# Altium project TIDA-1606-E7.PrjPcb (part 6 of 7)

## Sheet TIDA-1606-Control-Interface-E7.SchDoc
size A2; Date: Not shown in title block; ApprovedBy: Not shown in title block; CheckedBy: Not shown in title block; Author: Not shown in title block; CompanyName: Not shown in title block; Engineer: Not shown in title block; Organization: Not shown in title block; Address1: Not shown in title block; Address2: Not shown in title block; Address3: Not shown in title block; Address4: Not shown in title block; DocumentNumber: 16; Revision: Use project parameter SCH_Rev; SheetNumber: 16; SheetTotal: 16; PageSetup: Record=PageOptions¦CenterHorizontal=True¦CenterVertical=True¦PrintScale=0.69¦XCorrection=1.00¦YCorrection=1.00¦PrintKind=0¦BorderSize=5000000¦LeftOffset=0¦BottomOffset=0¦Orientation=2¦PaperLength=1000¦PaperWidth=1000¦Scale=100¦PaperSource=15¦PrintQuality=600¦MediaType=1¦DitherType=10¦PaperKind=Letter¦PrintScaleMode=1
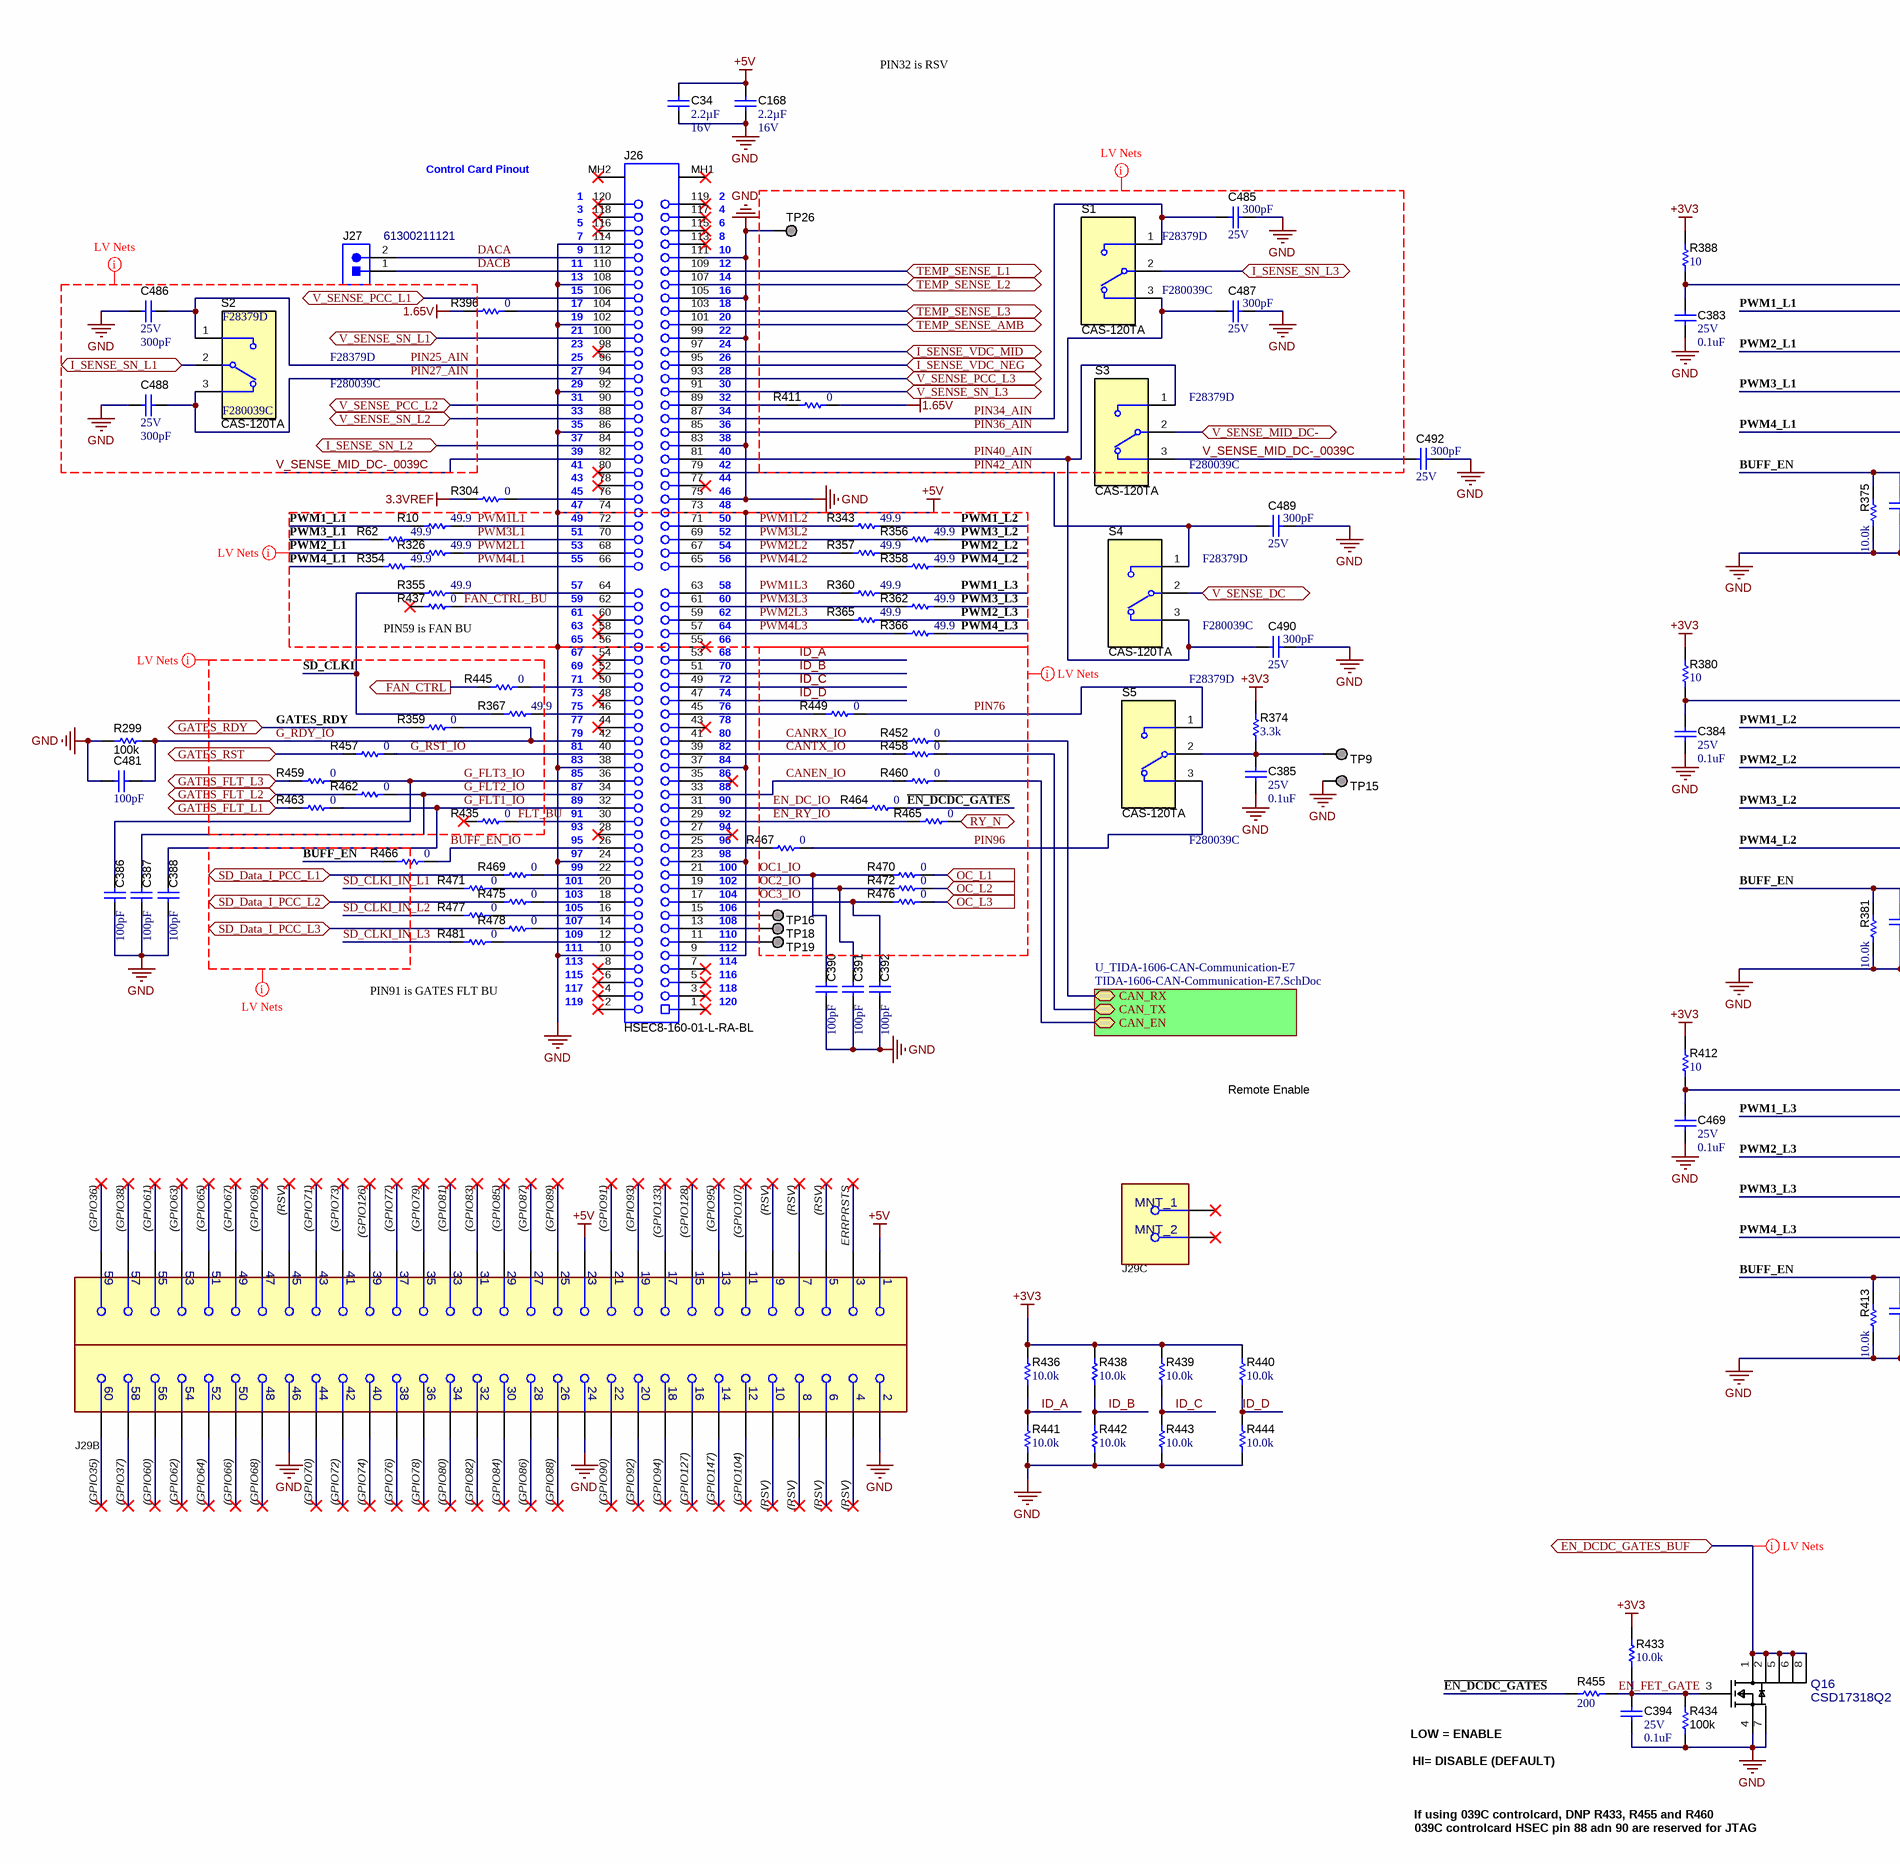
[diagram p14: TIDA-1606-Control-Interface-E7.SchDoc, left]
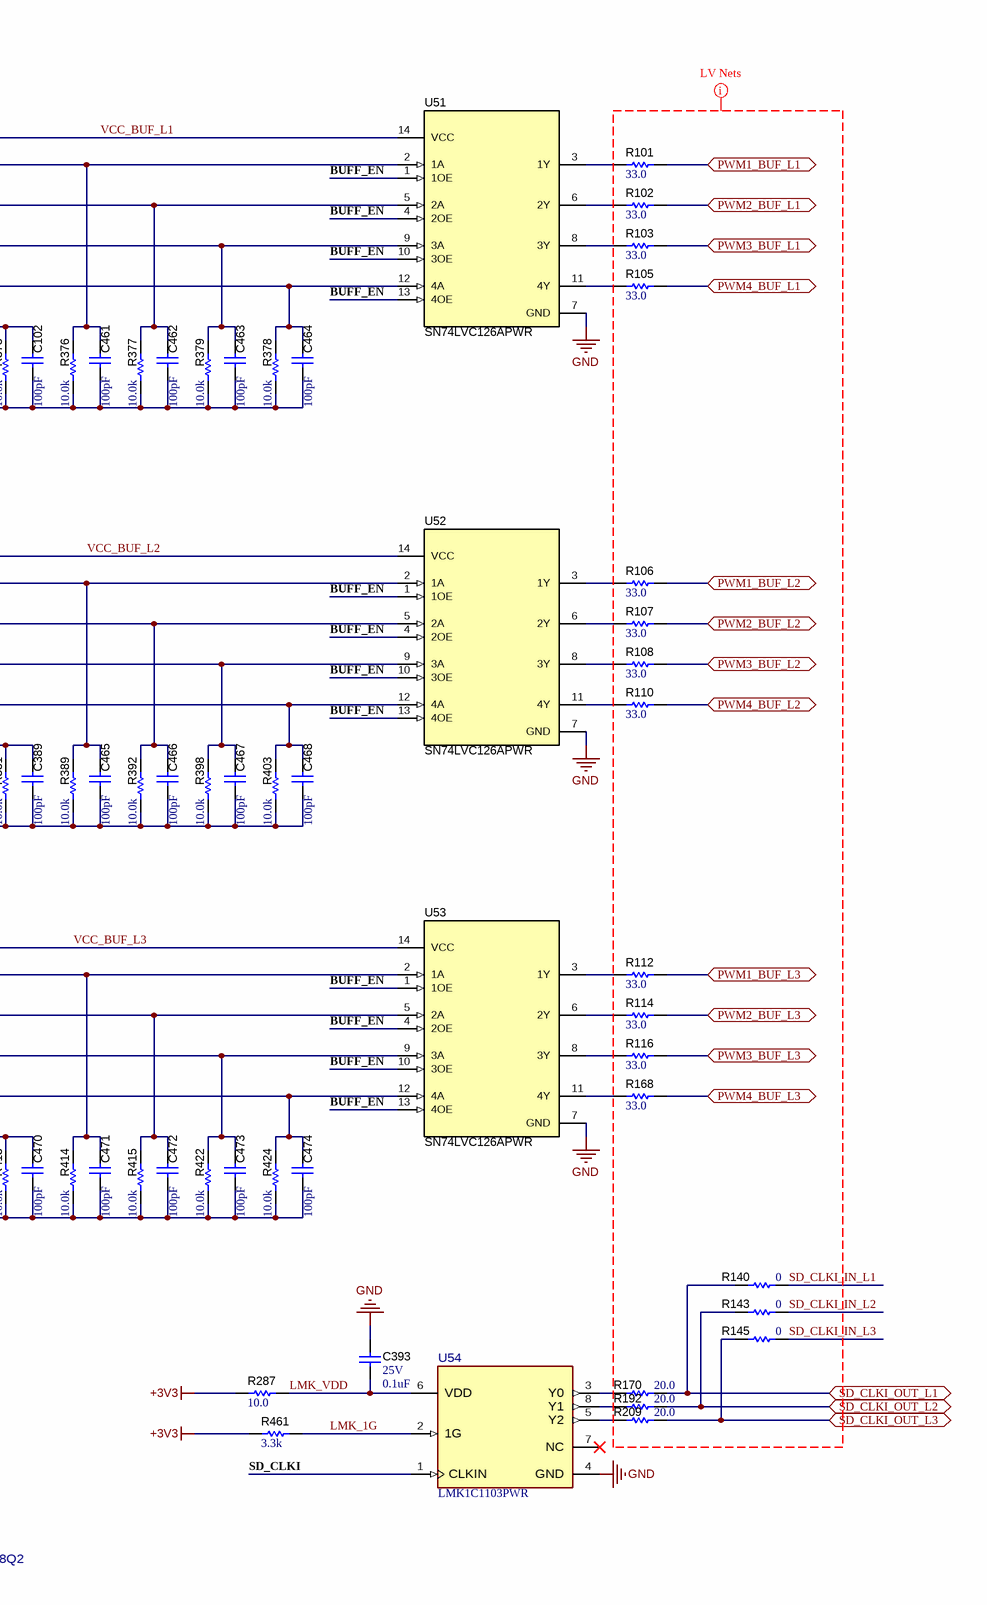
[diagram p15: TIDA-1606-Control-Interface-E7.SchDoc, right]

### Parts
C34  Cap_F: 2.2µF  VDC_V: 16V  [0603L]  (hidden comment: EMK107BB7225KA-T)
C102  ValueDisplayed: 100pF  [0402L]  (hidden comment: GRM1555C1H101JA01D)
C168  Cap_F: 2.2µF  VDC_V: 16V  [0603L]  (hidden comment: EMK107BB7225KA-T)
C383  VDC_V: 25V  ValueDisplayed: 0.1uF  [0402L]  (hidden comment: GRM155R71E104KE14D)
C384  VDC_V: 25V  ValueDisplayed: 0.1uF  [0402L]  (hidden comment: GRM155R71E104KE14D)
C385  VDC_V: 25V  ValueDisplayed: 0.1uF  [0402L]  (hidden comment: GRM155R71E104KE14D)
C386  ValueDisplayed: 100pF  [0402L]  (hidden comment: GRM1555C1H101JA01D)
C387  ValueDisplayed: 100pF  [0402L]  (hidden comment: GRM1555C1H101JA01D)
C388  ValueDisplayed: 100pF  [0402L]  (hidden comment: GRM1555C1H101JA01D)
C389  ValueDisplayed: 100pF  [0402L]  (hidden comment: GRM1555C1H101JA01D)
C390  ValueDisplayed: 100pF  [0402L]  (hidden comment: GRM1555C1H101JA01D)
C391  ValueDisplayed: 100pF  [0402L]  (hidden comment: GRM1555C1H101JA01D)
C392  ValueDisplayed: 100pF  [0402L]  (hidden comment: GRM1555C1H101JA01D)
C393  VDC_V: 25V  ValueDisplayed: 0.1uF  [0402L]  (hidden comment: GRM155R71E104KE14D)
C394  VDC_V: 25V  ValueDisplayed: 0.1uF  [0402L]  (hidden comment: GRM155R71E104KE14D)
C461  ValueDisplayed: 100pF  [0402L]  (hidden comment: GRM1555C1H101JA01D)
C462  ValueDisplayed: 100pF  [0402L]  (hidden comment: GRM1555C1H101JA01D)
C463  ValueDisplayed: 100pF  [0402L]  (hidden comment: GRM1555C1H101JA01D)
C464  ValueDisplayed: 100pF  [0402L]  (hidden comment: GRM1555C1H101JA01D)
C465  ValueDisplayed: 100pF  [0402L]  (hidden comment: GRM1555C1H101JA01D)
C466  ValueDisplayed: 100pF  [0402L]  (hidden comment: GRM1555C1H101JA01D)
C467  ValueDisplayed: 100pF  [0402L]  (hidden comment: GRM1555C1H101JA01D)
C468  ValueDisplayed: 100pF  [0402L]  (hidden comment: GRM1555C1H101JA01D)
C469  VDC_V: 25V  ValueDisplayed: 0.1uF  [0402L]  (hidden comment: GRM155R71E104KE14D)
C470  ValueDisplayed: 100pF  [0402L]  (hidden comment: GRM1555C1H101JA01D)
C471  ValueDisplayed: 100pF  [0402L]  (hidden comment: GRM1555C1H101JA01D)
C472  ValueDisplayed: 100pF  [0402L]  (hidden comment: GRM1555C1H101JA01D)
C473  ValueDisplayed: 100pF  [0402L]  (hidden comment: GRM1555C1H101JA01D)
C474  ValueDisplayed: 100pF  [0402L]  (hidden comment: GRM1555C1H101JA01D)
C481  ValueDisplayed: 100pF  [0402L]  (hidden comment: GRM1555C1H101JA01D)
C485  VDC_V: 25V  ValueDisplayed: 300pF  [0402L]  (hidden comment: GRM1555C1E301JA01D)
C486  VDC_V: 25V  ValueDisplayed: 300pF  [0402L]  (hidden comment: GRM1555C1E301JA01D)
C487  VDC_V: 25V  ValueDisplayed: 300pF  [0402L]  (hidden comment: GRM1555C1E301JA01D)
C488  VDC_V: 25V  ValueDisplayed: 300pF  [0402L]  (hidden comment: GRM1555C1E301JA01D)
C489  VDC_V: 25V  ValueDisplayed: 300pF  [0402L]  (hidden comment: GRM1555C1E301JA01D)
C490  VDC_V: 25V  ValueDisplayed: 300pF  [0402L]  (hidden comment: GRM1555C1E301JA01D)
C492  VDC_V: 25V  ValueDisplayed: 300pF  [0402L]  (hidden comment: GRM1555C1E301JA01D)
J26  HSEC8-160-01-L-RA-BL  [Samtec_HSEC8-160-01-x-RA-BL]
J27  61300211121  [WURTH_61300211121]
J29  HSEC8-130-01-L-RA  [FP-HSEC8-130-01-L-RA_HDR60-MFG]  (value not drawn)  (parts A,B,C of 3)
Q16  CSD17318Q2  [FP-CSD17318Q2_WSON6-MFG]
R10  ValueDisplayed: 49.9  [0402L]  (hidden comment: ERJ-2RKF49R9X)
R62  ValueDisplayed: 49.9  [0402L]  (hidden comment: ERJ-2RKF49R9X)
R101  ValueDisplayed: 33.0  [0402L]  (hidden comment: ERJ-2RKF33R0X)
R102  ValueDisplayed: 33.0  [0402L]  (hidden comment: ERJ-2RKF33R0X)
R103  ValueDisplayed: 33.0  [0402L]  (hidden comment: ERJ-2RKF33R0X)
R105  ValueDisplayed: 33.0  [0402L]  (hidden comment: ERJ-2RKF33R0X)
R106  ValueDisplayed: 33.0  [0402L]  (hidden comment: ERJ-2RKF33R0X)
R107  ValueDisplayed: 33.0  [0402L]  (hidden comment: ERJ-2RKF33R0X)
R108  ValueDisplayed: 33.0  [0402L]  (hidden comment: ERJ-2RKF33R0X)
R110  ValueDisplayed: 33.0  [0402L]  (hidden comment: ERJ-2RKF33R0X)
R112  ValueDisplayed: 33.0  [0402L]  (hidden comment: ERJ-2RKF33R0X)
R114  ValueDisplayed: 33.0  [0402L]  (hidden comment: ERJ-2RKF33R0X)
R116  ValueDisplayed: 33.0  [0402L]  (hidden comment: ERJ-2RKF33R0X)
R140  ValueDisplayed: 0  [0402L]  (hidden comment: RC0402JR-070RL)
R143  ValueDisplayed: 0  [0402L]  (hidden comment: RC0402JR-070RL)
R145  ValueDisplayed: 0  [0402L]  (hidden comment: RC0402JR-070RL)
R168  ValueDisplayed: 33.0  [0402L]  (hidden comment: ERJ-2RKF33R0X)
R170  ValueDisplayed: 20.0  [0402L]  (hidden comment: CRCW040220R0FKED)
R192  ValueDisplayed: 20.0  [0402L]  (hidden comment: CRCW040220R0FKED)
R209  ValueDisplayed: 20.0  [0402L]  (hidden comment: CRCW040220R0FKED)
R287  ValueDisplayed: 10.0  [CPF0402]  (hidden comment: CPF0402B10RE1)
R299  ValueDisplayed: 100k  [0402L]  (hidden comment: ERJ-2GEJ104X)
R304  ValueDisplayed: 0  [0402L]  (hidden comment: RC0402JR-070RL)
R326  ValueDisplayed: 49.9  [0402L]  (hidden comment: ERJ-2RKF49R9X)
R343  ValueDisplayed: 49.9  [0402L]  (hidden comment: ERJ-2RKF49R9X)
R354  ValueDisplayed: 49.9  [0402L]  (hidden comment: ERJ-2RKF49R9X)
R355  ValueDisplayed: 49.9  [0402L]  (hidden comment: ERJ-2RKF49R9X)
R356  ValueDisplayed: 49.9  [0402L]  (hidden comment: ERJ-2RKF49R9X)
R357  ValueDisplayed: 49.9  [0402L]  (hidden comment: ERJ-2RKF49R9X)
R358  ValueDisplayed: 49.9  [0402L]  (hidden comment: ERJ-2RKF49R9X)
R359  ValueDisplayed: 0  [0402L]  (hidden comment: RC0402JR-070RL)
R360  ValueDisplayed: 49.9  [0402L]  (hidden comment: ERJ-2RKF49R9X)
R362  ValueDisplayed: 49.9  [0402L]  (hidden comment: ERJ-2RKF49R9X)
R365  ValueDisplayed: 49.9  [0402L]  (hidden comment: ERJ-2RKF49R9X)
R366  ValueDisplayed: 49.9  [0402L]  (hidden comment: ERJ-2RKF49R9X)
R367  ValueDisplayed: 49.9  [0402L]  (hidden comment: ERJ-2RKF49R9X)
R374  ValueDisplayed: 3.3k  [0402L]  (hidden comment: CRCW04023K30JNED)
R375  ValueDisplayed: 10.0k  [0402L]  (hidden comment: CRCW040210K0FKED)
R376  ValueDisplayed: 10.0k  [0402L]  (hidden comment: CRCW040210K0FKED)
R377  ValueDisplayed: 10.0k  [0402L]  (hidden comment: CRCW040210K0FKED)
R378  ValueDisplayed: 10.0k  [0402L]  (hidden comment: CRCW040210K0FKED)
R379  ValueDisplayed: 10.0k  [0402L]  (hidden comment: CRCW040210K0FKED)
R380  ValueDisplayed: 10  [0402L]  (hidden comment: CRCW040210R0JNED)
R381  ValueDisplayed: 10.0k  [0402L]  (hidden comment: CRCW040210K0FKED)
R388  ValueDisplayed: 10  [0402L]  (hidden comment: CRCW040210R0JNED)
R389  ValueDisplayed: 10.0k  [0402L]  (hidden comment: CRCW040210K0FKED)
R392  ValueDisplayed: 10.0k  [0402L]  (hidden comment: CRCW040210K0FKED)
R396  ValueDisplayed: 0  [0402L]  (hidden comment: RC0402JR-070RL)
R398  ValueDisplayed: 10.0k  [0402L]  (hidden comment: CRCW040210K0FKED)
R403  ValueDisplayed: 10.0k  [0402L]  (hidden comment: CRCW040210K0FKED)
R411  ValueDisplayed: 0  [0402L]  (hidden comment: RC0402JR-070RL)
R412  ValueDisplayed: 10  [0402L]  (hidden comment: CRCW040210R0JNED)
R413  ValueDisplayed: 10.0k  [0402L]  (hidden comment: CRCW040210K0FKED)
R414  ValueDisplayed: 10.0k  [0402L]  (hidden comment: CRCW040210K0FKED)
R415  ValueDisplayed: 10.0k  [0402L]  (hidden comment: CRCW040210K0FKED)
R422  ValueDisplayed: 10.0k  [0402L]  (hidden comment: CRCW040210K0FKED)
R424  ValueDisplayed: 10.0k  [0402L]  (hidden comment: CRCW040210K0FKED)
R433  ValueDisplayed: 10.0k  [0402L]  (hidden comment: CRCW040210K0FKED)
R434  ValueDisplayed: 100k  [0402S]  (hidden comment: ERJ-2GEJ104X)
R435  ValueDisplayed: 0  [0402L]  (hidden comment: RC0402JR-070RL)
R436  ValueDisplayed: 10.0k  [0402L]  (hidden comment: CRCW040210K0FKED)
R437  ValueDisplayed: 0  [0402L]  (hidden comment: RC0402JR-070RL)
R438  ValueDisplayed: 10.0k  [0402L]  (hidden comment: CRCW040210K0FKED)
R439  ValueDisplayed: 10.0k  [0402L]  (hidden comment: CRCW040210K0FKED)
R440  ValueDisplayed: 10.0k  [0402L]  (hidden comment: CRCW040210K0FKED)
R441  ValueDisplayed: 10.0k  [0402L]  (hidden comment: CRCW040210K0FKED)
R442  ValueDisplayed: 10.0k  [0402L]  (hidden comment: CRCW040210K0FKED)
R443  ValueDisplayed: 10.0k  [0402L]  (hidden comment: CRCW040210K0FKED)
R444  ValueDisplayed: 10.0k  [0402L]  (hidden comment: CRCW040210K0FKED)
R445  ValueDisplayed: 0  [0402L]  (hidden comment: RC0402JR-070RL)
R449  ValueDisplayed: 0  [0402L]  (hidden comment: RC0402JR-070RL)
R452  ValueDisplayed: 0  [0402L]  (hidden comment: RC0402JR-070RL)
R455  ValueDisplayed: 200  [0402L]  (hidden comment: CRCW0402200RJNED)
R457  ValueDisplayed: 0  [0402L]  (hidden comment: RC0402JR-070RL)
R458  ValueDisplayed: 0  [0402L]  (hidden comment: RC0402JR-070RL)
R459  ValueDisplayed: 0  [0402L]  (hidden comment: RC0402JR-070RL)
R460  ValueDisplayed: 0  [0402L]  (hidden comment: RC0402JR-070RL)
R461  ValueDisplayed: 3.3k  [0402L]  (hidden comment: CRCW04023K30JNED)
R462  ValueDisplayed: 0  [0402L]  (hidden comment: RC0402JR-070RL)
R463  ValueDisplayed: 0  [0402L]  (hidden comment: RC0402JR-070RL)
R464  ValueDisplayed: 0  [0402L]  (hidden comment: RC0402JR-070RL)
R465  ValueDisplayed: 0  [0402L]  (hidden comment: RC0402JR-070RL)
R466  ValueDisplayed: 0  [0402L]  (hidden comment: RC0402JR-070RL)
R467  ValueDisplayed: 0  [0402L]  (hidden comment: RC0402JR-070RL)
R469  ValueDisplayed: 0  [0402L]  (hidden comment: RC0402JR-070RL)
R470  ValueDisplayed: 0  [0402L]  (hidden comment: RC0402JR-070RL)
R471  ValueDisplayed: 0  [0402L]  (hidden comment: RC0402JR-070RL)
R472  ValueDisplayed: 0  [0402L]  (hidden comment: RC0402JR-070RL)
R475  ValueDisplayed: 0  [0402L]  (hidden comment: RC0402JR-070RL)
R476  ValueDisplayed: 0  [0402L]  (hidden comment: RC0402JR-070RL)
R477  ValueDisplayed: 0  [0402L]  (hidden comment: RC0402JR-070RL)
R478  ValueDisplayed: 0  [0402L]  (hidden comment: RC0402JR-070RL)
R481  ValueDisplayed: 0  [0402L]  (hidden comment: RC0402JR-070RL)
S1  CAS-120TA  [SW_CAS-120TA]
S2  CAS-120TA  [SW_CAS-120TA]
S3  CAS-120TA  [SW_CAS-120TA]
S4  CAS-120TA  [SW_CAS-120TA]
S5  CAS-120TA  [SW_CAS-120TA]
TP9  S2751-46R  [Harwin_S2751-46R]  (value not drawn)
TP15  S2751-46R  [Harwin_S2751-46R]  (value not drawn)
TP16  TP_SM_1MM  [TP_SM_1MM]  (value not drawn)  (no BOM)
TP18  TP_SM_1MM  [TP_SM_1MM]  (value not drawn)  (no BOM)
TP19  TP_SM_1MM  [TP_SM_1MM]  (value not drawn)  (no BOM)
TP26  S2751-46R  [Harwin_S2751-46R]  (value not drawn)
U51  SN74LVC126APWR  [PW0014A_N]
U52  SN74LVC126APWR  [PW0014A_N]
U53  SN74LVC126APWR  [PW0014A_N]
U54  LMK1C1103PWR  [PW0008A-MFG]

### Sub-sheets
U_TIDA-1606-CAN-Communication-E7 = TIDA-1606-CAN-Communication-E7.SchDoc: CAN_TX (bidir), CAN_EN (bidir), CAN_RX (bidir)

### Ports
EN_DCDC_GATES_BUF (bidir), FAN_CTRL (out), GATES_FLT_L1 (bidir), GATES_FLT_L2 (bidir), GATES_FLT_L3 (bidir), GATES_RDY (bidir), GATES_RST (bidir), I_SENSE_SN_L1 (bidir), I_SENSE_SN_L2 (bidir), I_SENSE_SN_L3 (bidir), I_SENSE_VDC_MID (bidir), I_SENSE_VDC_NEG (bidir), OC_L1 (in), OC_L2 (in), OC_L3 (in), PWM1_BUF_L1 (bidir), PWM1_BUF_L2 (bidir), PWM1_BUF_L3 (bidir), PWM2_BUF_L1 (bidir), PWM2_BUF_L2 (bidir), PWM2_BUF_L3 (bidir), PWM3_BUF_L1 (bidir), PWM3_BUF_L2 (bidir), PWM3_BUF_L3 (bidir), PWM4_BUF_L1 (bidir), PWM4_BUF_L2 (bidir), PWM4_BUF_L3 (bidir), RY_N (bidir), SD_CLKI_OUT_L1 (bidir), SD_CLKI_OUT_L2 (bidir), SD_CLKI_OUT_L3 (bidir), SD_Data_I_PCC_L1 (bidir), SD_Data_I_PCC_L2 (bidir), SD_Data_I_PCC_L3 (bidir), TEMP_SENSE_AMB (bidir), TEMP_SENSE_L1 (bidir), TEMP_SENSE_L2 (bidir), TEMP_SENSE_L3 (bidir), V_SENSE_DC (bidir), V_SENSE_MID_DC- (bidir), V_SENSE_PCC_L1 (bidir), V_SENSE_PCC_L2 (bidir), V_SENSE_PCC_L3 (bidir), V_SENSE_SN_L1 (bidir), V_SENSE_SN_L2 (bidir), V_SENSE_SN_L3 (bidir)

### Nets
1.65V: R396.1 R411.2
3.3VREF: R304.1
+3V3: R287.1 R374.2 R380.2 R388.2 R412.2 R433.2 R436.2 R438.2 R439.2 R440.2 R461.2
+5V: C34.1 C168.1 J26.9 J26.23 J26.37 J26.73 J29.1 J29.23
GND: C34.2 C102.2 C168.2 C383.1 C384.1 C385.2 C386.2 C387.2 C388.2 C389.2 C390.2 C391.2 C392.2 C393.1 C394.2 C461.2 C462.2 C463.2 C464.2 C465.2 C466.2 C467.2 C468.2 C469.1 C470.2 C471.2 C472.2 C473.2 C474.2 C481.1 C485.2 C486.2 C487.2 C488.2 C489.2 C490.2 C492.2 J26.10 J26.24 J26.38 J26.56 J26.74 J26.75 J26.83 J26.86 J26.92 J26.99 J26.102 J26.105 J26.108 J26.111 J26.114 J29.2 J29.24 J29.46 Q16.4(S) Q16.7(S) R299.2 R375.1 R376.1 R377.1 R378.1 R379.1 R381.1 R389.1 R392.1 R398.1 R403.1 R413.1 R414.1 R415.1 R422.1 R424.1 R434.2 R441.1 R442.1 R443.1 R444.1 TP15.1 TP26.1 U51.7(GND) U52.7(GND) U53.7(GND) U54.4(GND)
~{EN_DCDC_GATES}: R455.1 R464.2
BUFF_EN: C102.1 C389.1 C470.1 R375.2 R381.2 R413.2 R466.1 U51.1(1OE) U51.4(2OE) U51.10(3OE) U51.13(4OE) U52.1(1OE) U52.4(2OE) U52.10(3OE) U52.13(4OE) U53.1(1OE) U53.4(2OE) U53.10(3OE) U53.13(4OE)
BUFF_EN_IO: J26.26 R466.2
CAN_EN: R460.2 ; sheet U_TIDA-1606-CAN-Communication-E7/CAN_EN
CAN_RX: R452.2 ; sheet U_TIDA-1606-CAN-Communication-E7/CAN_RX
CAN_TX: R458.2 ; sheet U_TIDA-1606-CAN-Communication-E7/CAN_TX
CANEN_IO: J26.33 R460.1
CANRX_IO: J26.41 R452.1
CANTX_IO: J26.39 R458.1
DACA: J26.112 J27.2
DACB: J26.110 J27.1
EN_DC_IO: J26.31 R464.1
EN_DCDC_GATES_BUF: Q16.1(D) Q16.2(D) Q16.5(D) Q16.6(D) Q16.8(D) ; port EN_DCDC_GATES_BUF
EN_FET_GATE: C394.1 Q16.3(G) R433.1 R434.1 R455.2
EN_RY_IO: J26.29 R465.1
FAN_CTRL: R445.1 ; port FAN_CTRL
FAN_CTRL_BU: J26.62 R437.2
FLT_BU: J26.30 R435.2
G_FLT1_IO: C388.1 J26.32 R463.2
G_FLT2_IO: C387.1 J26.34 R462.2
G_FLT3_IO: C386.1 J26.36 R459.2
G_RDY_IO: C481.2 J26.42 R299.1 R359.2
G_RST_IO: J26.40 R457.2
GATES_FLT_L1: R463.1 ; port GATES_FLT_L1
GATES_FLT_L2: R462.1 ; port GATES_FLT_L2
GATES_FLT_L3: R459.1 ; port GATES_FLT_L3
GATES_RDY: R359.1 ; port GATES_RDY
GATES_RST: R457.1 ; port GATES_RST
I_SENSE_SN_L1: S2.2 ; port I_SENSE_SN_L1
I_SENSE_SN_L2: J26.84 ; port I_SENSE_SN_L2
I_SENSE_SN_L3: S1.2 ; port I_SENSE_SN_L3
I_SENSE_VDC_MID: J26.97 ; port I_SENSE_VDC_MID
I_SENSE_VDC_NEG: J26.95 ; port I_SENSE_VDC_NEG
ID_A: J26.53 R436.1 R441.2
ID_B: J26.51 R438.1 R442.2
ID_C: J26.49 R439.1 R443.2
ID_D: J26.47 R440.1 R444.2
LMK_1G: R461.1 U54.2(1G)
LMK_VDD: C393.2 R287.2 U54.6(VDD)
OC1_IO: C390.1 J26.21 R470.1
OC2_IO: C391.1 J26.19 R472.1
OC3_IO: C392.1 J26.17 R476.1
OC_L1: R470.2 ; port OC_L1
OC_L2: R472.2 ; port OC_L2
OC_L3: R476.2 ; port OC_L3
PIN25_AIN: C486.1 J26.96 S2.1
PIN27_AIN: C488.1 J26.94 S2.3
PIN34_AIN: C485.1 J26.87 S1.1
PIN36_AIN: C487.1 J26.85 S1.3
PIN40_AIN: C490.1 J26.81 S3.1 S4.3
PIN42_AIN: C489.1 J26.79 S4.1
PIN76: R449.2 S5.1
PIN96: R467.2 S5.3
PWM1_BUF_L1: R101.2 ; port PWM1_BUF_L1
PWM1_BUF_L2: R106.2 ; port PWM1_BUF_L2
PWM1_BUF_L3: R112.2 ; port PWM1_BUF_L3
PWM1_L1: C461.1 R10.1 R376.2 U51.2(1A)
PWM1_L2: C465.1 R343.2 R389.2 U52.2(1A)
PWM1_L3: C471.1 R360.2 R414.2 U53.2(1A)
PWM1L1: J26.72 R10.2
PWM1L2: J26.71 R343.1
PWM1L3: J26.63 R360.1
PWM2_BUF_L1: R102.2 ; port PWM2_BUF_L1
PWM2_BUF_L2: R107.2 ; port PWM2_BUF_L2
PWM2_BUF_L3: R114.2 ; port PWM2_BUF_L3
PWM2_L1: C462.1 R326.1 R377.2 U51.5(2A)
PWM2_L2: C466.1 R357.2 R392.2 U52.5(2A)
PWM2_L3: C472.1 R365.2 R415.2 U53.5(2A)
PWM2L1: J26.68 R326.2
PWM2L2: J26.67 R357.1
PWM2L3: J26.59 R365.1
PWM3_BUF_L1: R103.2 ; port PWM3_BUF_L1
PWM3_BUF_L2: R108.2 ; port PWM3_BUF_L2
PWM3_BUF_L3: R116.2 ; port PWM3_BUF_L3
PWM3_L1: C463.1 R62.1 R379.2 U51.9(3A)
PWM3_L2: C467.1 R356.2 R398.2 U52.9(3A)
PWM3_L3: C473.1 R362.2 R422.2 U53.9(3A)
PWM3L1: J26.70 R62.2
PWM3L2: J26.69 R356.1
PWM3L3: J26.61 R362.1
PWM4_BUF_L1: R105.2 ; port PWM4_BUF_L1
PWM4_BUF_L2: R110.2 ; port PWM4_BUF_L2
PWM4_BUF_L3: R168.2 ; port PWM4_BUF_L3
PWM4_L1: C464.1 R354.1 R378.2 U51.12(4A)
PWM4_L2: C468.1 R358.2 R403.2 U52.12(4A)
PWM4_L3: C474.1 R366.2 R424.2 U53.12(4A)
PWM4L1: J26.66 R354.2
PWM4L2: J26.65 R358.1
PWM4L3: J26.57 R366.1
RY_N: R465.2 ; port RY_N
SD_CLKI: R355.1 R367.1 U54.1(CLKIN)
SD_CLKI_IN_L1: R140.2 R471.1
SD_CLKI_IN_L2: R143.2 R477.1
SD_CLKI_IN_L3: R145.2 R481.1
SD_CLKI_OUT_L1: R140.1 R170.2 ; port SD_CLKI_OUT_L1
SD_CLKI_OUT_L2: R143.1 R192.2 ; port SD_CLKI_OUT_L2
SD_CLKI_OUT_L3: R145.1 R209.2 ; port SD_CLKI_OUT_L3
SD_Data_I_PCC_L1: R469.1 ; port SD_Data_I_PCC_L1
SD_Data_I_PCC_L2: R475.1 ; port SD_Data_I_PCC_L2
SD_Data_I_PCC_L3: R478.1 ; port SD_Data_I_PCC_L3
TEMP_SENSE_AMB: J26.101 ; port TEMP_SENSE_AMB
TEMP_SENSE_L1: J26.109 ; port TEMP_SENSE_L1
TEMP_SENSE_L2: J26.107 ; port TEMP_SENSE_L2
TEMP_SENSE_L3: J26.103 ; port TEMP_SENSE_L3
V_SENSE_DC: S4.2 ; port V_SENSE_DC
V_SENSE_MID_DC-: S3.2 ; port V_SENSE_MID_DC-
V_SENSE_MID_DC-_0039C: C492.1 J26.82 S3.3
V_SENSE_PCC_L1: J26.106 ; port V_SENSE_PCC_L1
V_SENSE_PCC_L2: J26.90 ; port V_SENSE_PCC_L2
V_SENSE_PCC_L3: J26.93 ; port V_SENSE_PCC_L3
V_SENSE_SN_L1: J26.100 ; port V_SENSE_SN_L1
V_SENSE_SN_L2: J26.88 ; port V_SENSE_SN_L2
V_SENSE_SN_L3: J26.91 ; port V_SENSE_SN_L3
VCC_BUF_L1: C383.2 R388.1 U51.14(VCC)
VCC_BUF_L2: C384.2 R380.1 U52.14(VCC)
VCC_BUF_L3: C469.2 R412.1 U53.14(VCC)
NetC385_1: C385.1 R374.1 S5.2 TP9.1
NetJ26_11: J26.11 TP19.1
NetJ26_12: J26.12 R481.2
NetJ26_13: J26.13 TP18.1
NetJ26_14: J26.14 R478.2
NetJ26_15: J26.15 TP16.1
NetJ26_16: J26.16 R477.2
NetJ26_18: J26.18 R475.2
NetJ26_20: J26.20 R471.2
NetJ26_22: J26.22 R469.2
NetJ26_25: J26.25 R467.1
NetJ26_45: J26.45 R449.1
NetJ26_46: J26.46 R367.2
NetJ26_50: J26.50 R445.2
NetJ26_64: J26.64 R355.2
NetJ26_76: J26.76 R304.2
NetJ26_89: J26.89 R411.1
NetJ26_104: J26.104 R396.2
NetR101_1: R101.1 U51.3(1Y)
NetR102_1: R102.1 U51.6(2Y)
NetR103_1: R103.1 U51.8(3Y)
NetR105_1: R105.1 U51.11(4Y)
NetR106_1: R106.1 U52.3(1Y)
NetR107_1: R107.1 U52.6(2Y)
NetR108_1: R108.1 U52.8(3Y)
NetR110_1: R110.1 U52.11(4Y)
NetR112_1: R112.1 U53.3(1Y)
NetR114_1: R114.1 U53.6(2Y)
NetR116_1: R116.1 U53.8(3Y)
NetR168_1: R168.1 U53.11(4Y)
NetR170_1: R170.1 U54.3(Y0)
NetR192_1: R192.1 U54.8(Y1)
NetR209_1: R209.1 U54.5(Y2)

Not connected (* = marked no-connect by the designer): J26 1* 2* 3* 4* 5* 6* 7* 8* 27* 28* 35* 43* 44* 48* 52* 54* 55* 58* 60* 77* 78* 80* 98* 113* 115* 116* 117* 118* 119* 120* MH1* MH2*; J29 3* 4* 5* 6* 7* 8* 9* 10* 11* 12* 13* 14* 15* 16* 17* 18* 19* 20* 21* 22* 25* 26* 27* 28* 29* 30* 31* 32* 33* 34* 35* 36* 37* 38* 39* 40* 41* 42* 43* 44* 45* 47* 48* 49* 50* 51* 52* 53* 54* 55* 56* 57* 58* 59* 60* 61(MNT_1)* 62(MNT_2)*; R435 1*; R437 1*; U54 7(NC)*

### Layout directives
net class LV Nets: 1.65V, GND, PIN25_AIN, PIN27_AIN, PIN34_AIN, PIN36_AIN, PIN40_AIN, PIN42_AIN, V_SENSE_MID_DC-_0039C
net class LV_DIGITAL: BUFF_EN, CANEN_IO, CANRX_IO, CANTX_IO, EN_DC_IO, EN_DCDC_GATES_BUF, EN_RY_IO, FLT_BU, G_FLT1_IO, G_FLT2_IO, G_FLT3_IO, G_RDY_IO, G_RST_IO, GATES_RDY, ID_A, ID_B, ID_C, ID_D, OC1_IO, OC2_IO, OC3_IO, PIN76, PIN96, PWM2_L1, SD_CLKI, SD_CLKI_IN_L1, SD_CLKI_IN_L2, SD_CLKI_IN_L3, ~{EN_DCDC_GATES}

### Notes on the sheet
- PIN32 is RSV
- Control Card Pinout
- (near J26) 1
- (near J26) 3
- (near J26) 5
- (near J26) 2
- 4
- 6
- (near J26) 7
- (near J26) 9
- (near J26) 11
- (near J26) 13
- (near J26) 15
- 8
- 10
- 12
- (near J26) 14
- (near J26) 16
- F28379D
- F280039C
- (near S2) F28379D
- (near J26) 17
- (near J26) 19
- (near J26) 21
- (near J26) 23
- (near J26) 25
- (near J26) 18
- (near J26) 22
- (near J26) 20
- (near J26) 24
- (near J26) 26
- (near S2) F280039C
- (near J26) 27
- (near J26) 29
- (near J26) 31
- (near J26) 33
- (near J26) 35
- (near J26) 28
- (near J26) 30
- (near J26) 32
- (near J26) 34
- (near J26) 36
- (near S3) F28379D
- (near J26) 37
- (near J26) 39
- (near J26) 41
- (near J26) 43
- (near J26) 45
- (near J26) 38
- (near J26) 40
- (near J26) 42
- (near J26) 44
- (near J26) 46
- (near J26) 47
- (near J26) 49
- (near J26) 51
- (near J26) 53
- (near J26) 55
- (near J26) 50
- (near J26) 48
- (near J26) 52
- (near J26) 54
- (near J26) 56
- (near R437) PIN59 is FAN BU
- (near J26) 59
- (near J26) 57
- (near J26) 61
- (near J26) 63
- (near J26) 58
- (near J26) 60
- (near J26) 62
- (near J26) 64
- (near C490) F280039C
- (near J26) 65
- 67
- 69
- 71
- 73
- (near J26) 66
- (near J26) 68
- (near J26) 70
- (near J26) 72
- (near J26) 74
- 75
- 77
- 79
- 81
- 83
- (near J26) 76
- (near J26) 78
- (near J26) 80
- (near J26) 82
- (near J26) 84
- (near J26) 85
- (near J26) 87
- (near J26) 89
- (near J26) 91
- 93
- (near J26) 86
- (near J26) 88
- 90
- 92
- 94
- 95
- 97
- 99
- 101
- 103
- 96
- 98
- 100
- 102
- 104
- 105
- 107
- 109
- 111
- 113
- 106
- 108
- 110
- 112
- 114
- PIN91 is GATES FLT BU
- 115
- (near J26) 117
- (near J26) 119
- 116
- 118
- (near J26) 120
- Remote Enable
- (near J29) (GPIO36)
- (near J29) (GPIO38)
- (near J29) (GPIO61)
- (near J29) (GPIO63)
- (near J29) (GPIO65)
- (near J29) (GPIO67)
- (near J29) (GPIO69)
- (RSV)
- (near J29) (GPIO71)
- (near J29) (GPIO73)
- (near J29) (GPIO126)
- (near J29) (GPIO77)
- (near J29) (GPIO79)
- (near J29) (GPIO81)
- (near J29) (GPIO83)
- (near J29) (GPIO85)
- (near J29) (GPIO87)
- (near J29) (GPIO89)
- (near J29) (GPIO91)
- (near J29) (GPIO93)
- (near J29) (GPIO133)
- (near J29) (GPIO128)
- (near J29) (GPIO95)
- (near J29) (GPIO107)
- (near J29) ERRPRSTS
- (near J29) (GPIO35)
- (near J29) (GPIO37)
- (near J29) (GPIO60)
- (near J29) (GPIO62)
- (near J29) (GPIO64)
- (near J29) (GPIO66)
- (near J29) (GPIO68)
- (near J29) (GPIO70)
- (near J29) (GPIO72)
- (near J29) (GPIO74)
- (near J29) (GPIO76)
- (near J29) (GPIO78)
- (near J29) (GPIO80)
- (near J29) (GPIO82)
- (near J29) (GPIO84)
- (near J29) (GPIO86)
- (near J29) (GPIO88)
- (near J29) (GPIO90)
- (near J29) (GPIO92)
- (near J29) (GPIO94)
- (near J29) (GPIO127)
- (near J29) (GPIO147)
- (near J29) (GPIO104)
- LOW = ENABLE
- HI= DISABLE (DEFAULT)
- If using 039C controlcard, DNP R433, R455 and R460
- 039C controlcard HSEC pin 88 adn 90 are reserved for JTAG

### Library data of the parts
C34 C168 = CMP-0007121-4: CAP, CERM, 2.2 uF, 16 V, +/- 10%, X7R, 0603; Manufacturer: Taiyo Yuden; TaMin_C: -55°C; Polarized: N; SizeAreaWB_mm2: 4.68; Value1: Unknown; U/M: EA; Value: 2.2uF; TaMax_C: 125°C; SizeZ_mm: 1; SizeX_mm: 1.6; SizeY_mm: 0.8; Cap_Case: 0603; SizeArea_mm2: 1.28; AEC Category: Q200
C102 C386-C392 C461-C468 C470-C474 C481 = CMP-0006410-2: CAP, CERM, 100 pF, 50 V, +/- 5%, C0G/NP0, 0402; Manufacturer: MuRata; TaMin_C: -55°C; Polarized: N; SizeAreaWB_mm2: 3; Value1: Unknown; U/M: EA; Value: 100pF; TaMax_C: 125°C; SizeZ_mm: 0.6; SizeX_mm: 1; SizeY_mm: 0.5; Cap_Case: 0402; Value2: 50V; AEC Category: Q200
C383-C385 C393 C394 C469 = CMP-0006659-2: CAP, CERM, 0.1 uF, 25 V, +/- 10%, X7R, 0402; Manufacturer: MuRata; TaMin_C: -55°C; Polarized: N; SizeAreaWB_mm2: 3; Value1: Unknown; U/M: EA; Value: 0.1uF; TaMax_C: 125°C; SizeZ_mm: 0.6; SizeX_mm: 1; SizeY_mm: 0.5; Cap_Case: 0402; Cap_F: 100nF; AEC Category: Q200
C485-C490 C492 = CMP-0006376-2: CAP, CERM, 300 pF, 25 V, +/- 5%, C0G/NP0, 0402; Manufacturer: MuRata; TaMin_C: -55°C; Polarized: N; SizeAreaWB_mm2: 3; Value1: Unknown; U/M: EA; Value: 300pF; TaMax_C: 125°C; SizeZ_mm: 0.6; SizeX_mm: 1; SizeY_mm: 0.5; Cap_Case: 0402; AEC Category: Q200
J26 = CMP-0085713-2: Receptacle, 0.8mm, 60x2, Gold with Tin tail, SMT; Manufacturer: Samtec; Gender: Female; Pitch_mm: 0.8; Row_Count: 2
J27 = CMP-0054794-2: Header, 2.54 mm, 2x1, Gold, TH; Manufacturer: Wurth Elektronik; Green_Lifecycle: Active; Green_REACh: Passed; Cert_UL: Y; Gender: Male; Pitch_mm: 2.54; Row_Count: 1; Shrouded: N
J29 = CMP-0092559-1: 60 Position Female Connector Non Specified - Dual Edge Gold 0.031" (0.80mm) Black; Manufacturer: Samtec; Row_Count: 2; SizeZ_mm: 5.33mm; Conn Orientation: Right Angle; Current_A: 2.8A; Voltage_V: 240V; Is Female: yes; AEC Qualified: No; DUT-Pitch_mm: 0.8mm
Q16 = CMP-0076725-1: 30-V N-Channel NexFET™ Power MOSFET; Manufacturer: Texas Instruments; VdsMax_V: 30V; SizeZ_mm: 0.8mm; ChMode: False; QgTyp_nC: 6nC @ 4.5V; Rdson45_ohm: 0.0139; Vgs_V: 10V; AEC Qualified: No; IdsMax_A: 10A
R10 R62 R326 R343 R354-R358 R360 R362 R365-R367 = CMP-0026703-1: RES, 49.9, 1%, 0.1 W, AEC-Q200 Grade 0, 0402; Manufacturer: Panasonic; Power_W: 100mW; TempCo: 100 ppm/C; Value_Code: 49R9; U/M: EA; Value: 49.9; EIA_Code: E96; SizeX_mm: 1; SizeY_mm: 0.5; SizeZ_mm: 0.6; Value2: 0.1W; AEC Qualified: Y; VDC_V: 50V; AEC Grade: 0; AEC Category: Q200
R101-R103 R105-R108 R110 R112 R114 R116 R168 = CMP-0026696-1: RES, 33.0, 1%, 0.1 W, 0402; Manufacturer: Panasonic; Power_W: 100mW; TempCo: 100 ppm/C; Value_Code: 33R0; U/M: EA; Value: 33.0; Res_ohm: 33; SizeX_mm: 1; SizeY_mm: 0.5; SizeZ_mm: 0.6; Value2: 0.1W; VDC_V: 50V; AEC Category: Q200
R140 R143 R145 R304 R359 R396 R411 R435 R437 R445 R449 R452 R457-R460 R462-R467 R469-R472 R475-R478 R481 = CMP-0027004-2: RES, 0, 5%, 0.063 W, 0402; Manufacturer: Yageo America; Power_W: 63mW; TempCo: 200 ppm/C; Value_Code: 0000; U/M: EA; Value: 0; EIA_Code: E24; SizeX_mm: 1; SizeY_mm: 0.5; SizeZ_mm: 0.6; Value2: 0.063W; VDC_V: 50V; AEC Category: Q200
R170 R192 R209 = CMP-0026164-2: RES, 20.0, 1%, 0.063 W, AEC-Q200 Grade 0, 0402; Manufacturer: Vishay-Dale; Power_W: 63mW; TempCo: 100 ppm/C; Value_Code: 20R0; Value: 20.0; EIA_Code: E96; Res_ohm: 20; SizeX_mm: 1; SizeY_mm: 0.5; SizeZ_mm: 0.6; Value2: 0.063W; AEC Qualified: Y; VDC_V: 50V; AEC Category: Q200; AEC Grade: 0
R287 = CMP-0026765-1: RES, 10.0, 0.1%, 0.063 W, 0402; Manufacturer: TE Connectivity; Power_W: 63mW; TempCo: 25 ppm/C; Value_Code: 10R0; U/M: EA; Value: 10.0; EIA_Code: E192; Res_ohm: 10; SizeX_mm: 1; SizeY_mm: 0.5; SizeZ_mm: 0.35; Value2: 0.063W; AEC Qualified: N; AEC Category: Q200
R299 R434 = CMP-0026995-2: RES, 100 k, 5%, 0.1 W, AEC-Q200 Grade 0, 0402; Manufacturer: Panasonic; Power_W: 100mW; TempCo: 200 ppm/C; U/M: EA; Value: 100k; EIA_Code: E24; SizeX_mm: 1; SizeY_mm: 0.5; SizeZ_mm: 0.6; Value2: 0.1W; AEC Qualified: Y; VDC_V: 50V; AEC Grade: 0; AEC Category: Q200
R374 R461 = CMP-0026918-5: RES, 3.3 k, 5%, 0.063 W, AEC-Q200 Grade 0, 0402; Manufacturer: Vishay-Dale; Power_W: 63mW; TempCo: 200 ppm/C; Value_Code: 3k30; Value: 3.3k; EIA_Code: E24; SizeX_mm: 1; SizeY_mm: 0.5; SizeZ_mm: 0.6; Value2: 0.063W; AEC Qualified: Y; VDC_V: 50V; AEC Category: Q200; AEC Grade: 0
R375-R379 R381 R389 R392 R398 R403 R413-R415 R422 R424 R433 R436 R438-R444 = CMP-0025958-3: RES, 10.0 k, 1%, 0.063 W, AEC-Q200 Grade 0, 0402; Manufacturer: Vishay-Dale; Power_W: 63mW; TempCo: 100 ppm/C; Value_Code: 10k0; Value: 10.0k; EIA_Code: E96; Res_ohm: 10k; SizeX_mm: 1; SizeY_mm: 0.5; SizeZ_mm: 0.6; Value2: 0.063W; AEC Qualified: Y; VDC_V: 50V; AEC Category: Q200; AEC Grade: 0
R380 R388 R412 = CMP-0026827-3: RES, 10, 5%, 0.063 W, AEC-Q200 Grade 0, 0402; Manufacturer: Vishay-Dale; Power_W: 63mW; TempCo: 200 ppm/C; Value_Code: 10R0; Value: 10; EIA_Code: E24; SizeX_mm: 1; SizeY_mm: 0.5; SizeZ_mm: 0.6; Value2: 0.063W; AEC Qualified: Y; VDC_V: 50V; AEC Category: Q200; AEC Grade: 0
R455 = CMP-0026874-3: RES, 200, 5%, 0.063 W, AEC-Q200 Grade 0, 0402; Manufacturer: Vishay-Dale; Power_W: 63mW; TempCo: 200 ppm/C; Value_Code: 200R; Value: 200; EIA_Code: E24; SizeX_mm: 1; SizeY_mm: 0.5; SizeZ_mm: 0.6; Value2: 0.063W; AEC Qualified: Y; VDC_V: 50V; AEC Category: Q200; AEC Grade: 0
S1-S5 = CMP-0002139-2: Switch, Slide, SPDT  100mA, SMT; Manufacturer: Copal Electronics; CurrentRating_mA: 100A; SwitchFunction: On-On; VDC_V: 6V; PositionCount: 1
TP9 TP15 TP26 = CMP-0003968-1: Test Point, SMT; Manufacturer: Harwin
TP16 TP18 TP19 = CMP-0003825-1: 1mm Test Point, SMT; Manufacturer: Any
U51-U53 = CMP-0066280-1: Quadruple Bus Buffer Gate with 3-State Outputs, PW0014A (TSSOP-14); Manufacturer: Texas Instruments; SizeArea_mm2: 32.0; SizeAreaWB_mm2: 58.8; SizeX_mm: 6.4; SizeY_mm: 5.0; SizeZ_mm: 1.2; CompType: IC; U/M: EA
U54 = CMP-0094559-1: Clock Clock Buffer IC 1:3 250 MHz 8-TSSOP; Manufacturer: Texas Instruments; TaMax_C: +125°C; Propagation Delay: 1.5ns; SizeZ_mm: 1.2mm; TJmax_C: +150°C; Number Of Inputs: 1; Max Supply Voltage: 3.465V; Min Supply Voltage: 1.71V; Standoff Height: 0.05mm; Number Of Outputs: 3; AEC Qualified: No; TaMin_C: -40°C; Logic Function: Non-Inverting; Nominal Supply Current: 8-33mA

## Sheet TIDA-1606-CAN-Communication-E7.SchDoc
size A3; Date: Not shown in title block; ApprovedBy: Not shown in title block; CheckedBy: Not shown in title block; Author: Not shown in title block; CompanyName: Not shown in title block; Engineer: Not shown in title block; Organization: Not shown in title block; Address1: Not shown in title block; Address2: Not shown in title block; Address3: Not shown in title block; Address4: Not shown in title block; DocumentNumber: 15; Revision: Use project parameter SCH_Rev; SheetNumber: 15; SheetTotal: 16; PageSetup: Record=PageOptions¦CenterHorizontal=True¦CenterVertical=True¦PrintScale=0.69¦XCorrection=1.00¦YCorrection=1.00¦PrintKind=0¦BorderSize=5000000¦LeftOffset=0¦BottomOffset=0¦Orientation=2¦PaperLength=1000¦PaperWidth=1000¦Scale=100¦PaperSource=15¦PrintQuality=600¦MediaType=1¦DitherType=10¦PaperKind=Letter¦PrintScaleMode=1
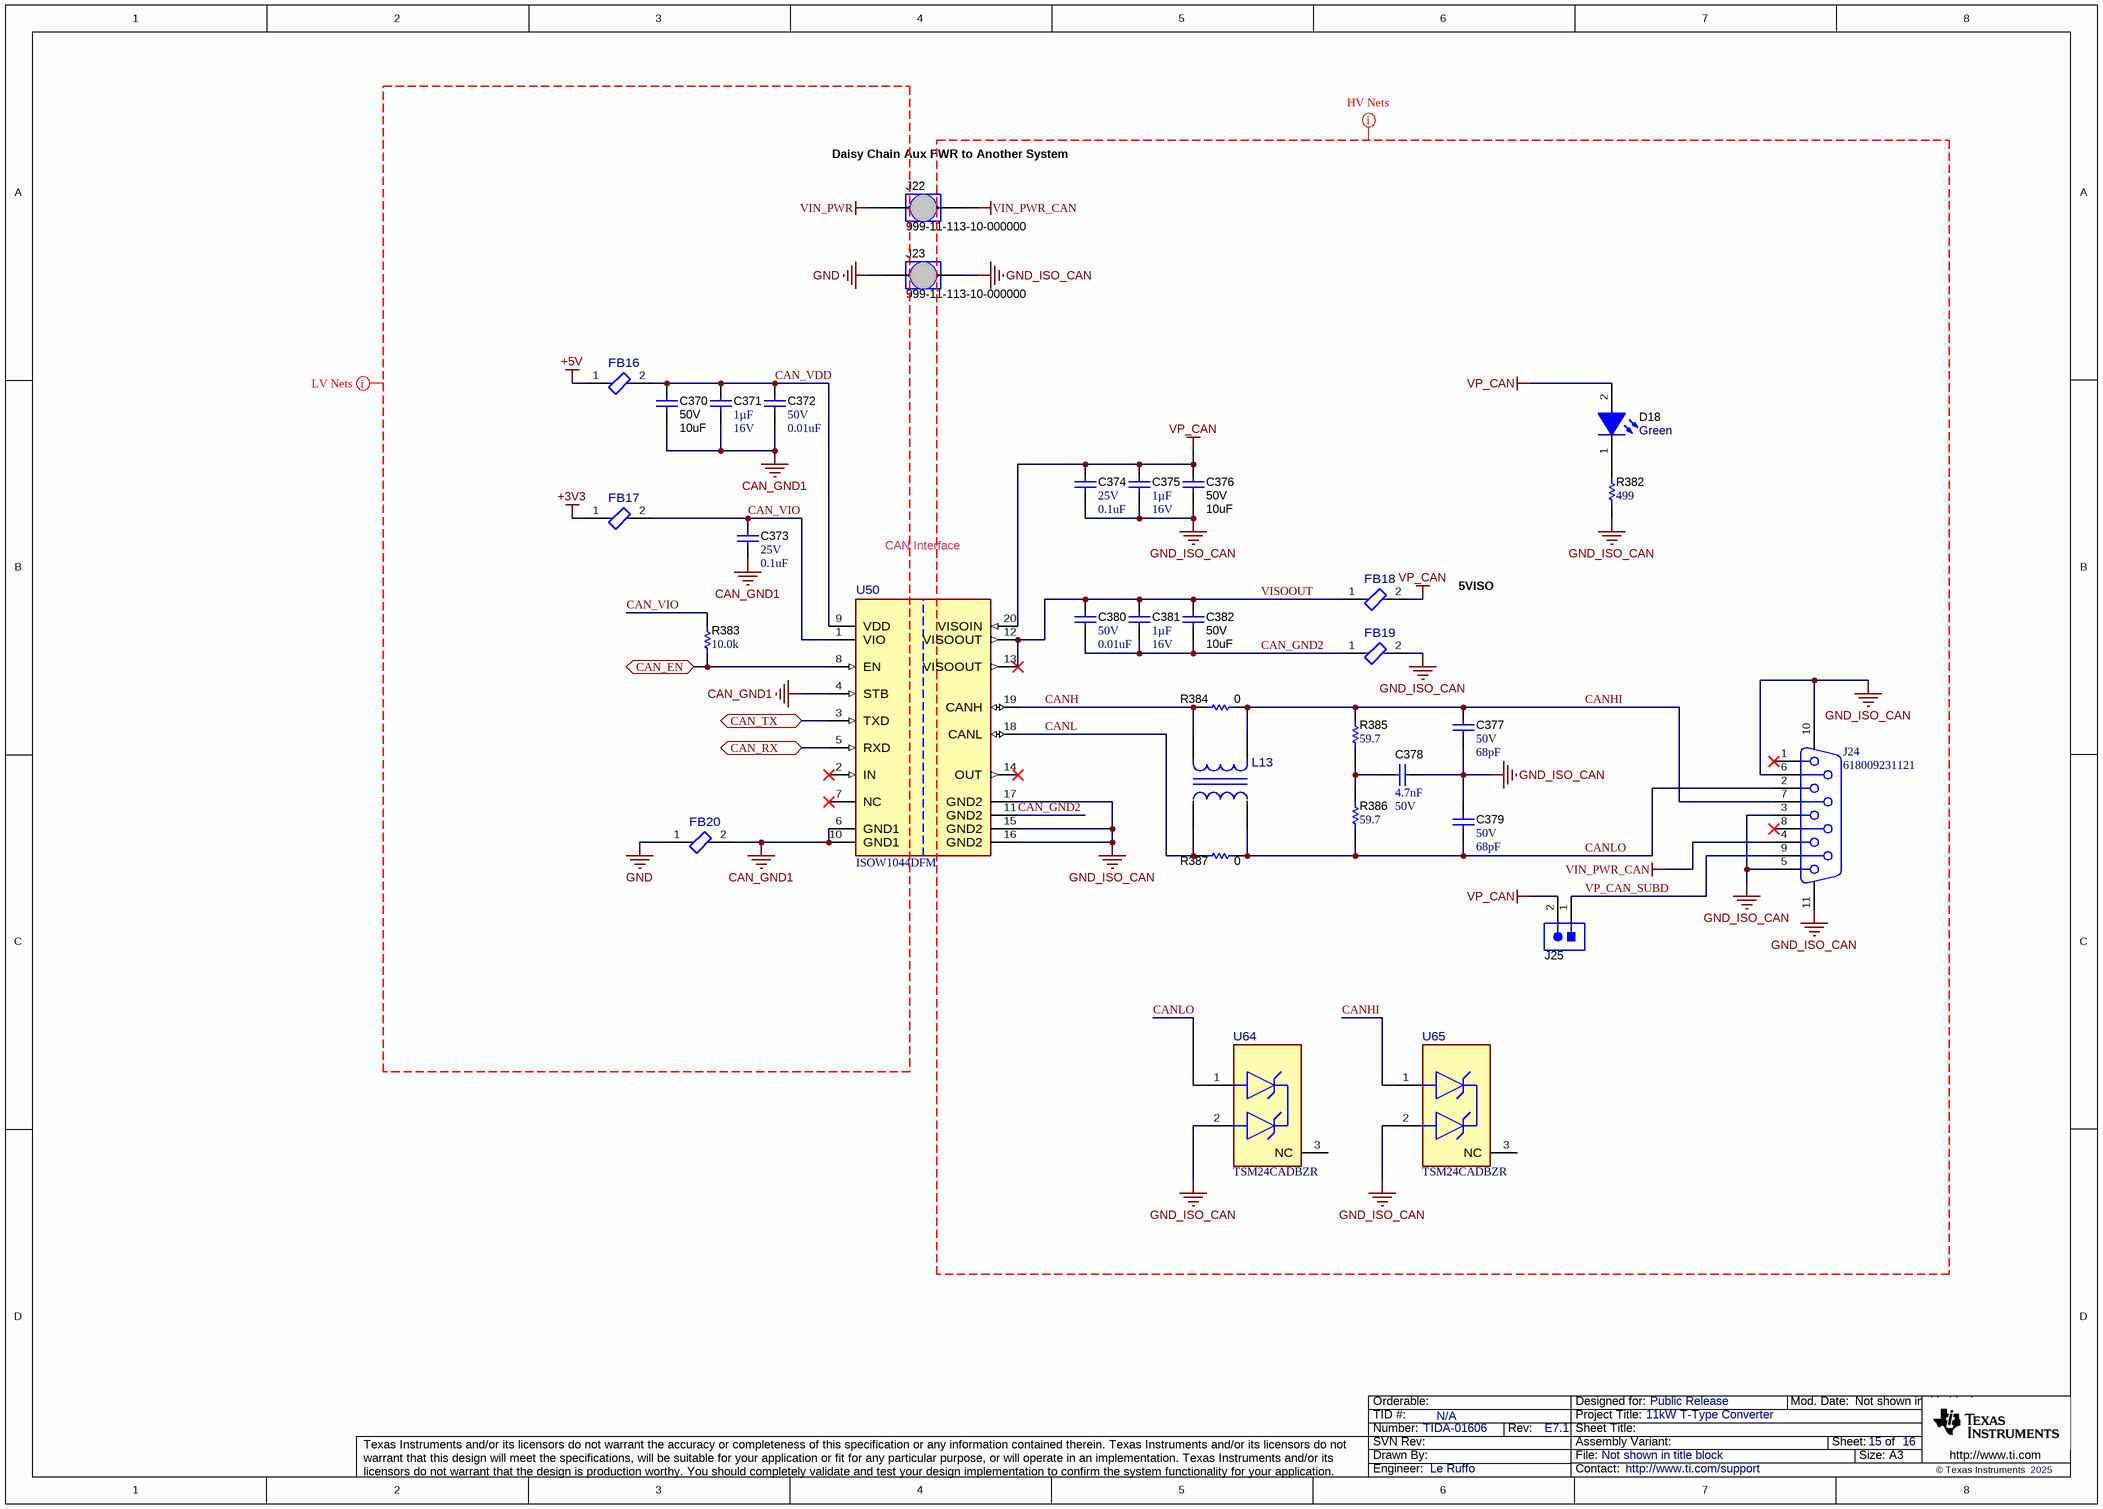
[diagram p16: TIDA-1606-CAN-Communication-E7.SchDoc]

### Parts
C370  VDC_V: 50V  ValueDisplayed: 10uF  [1206_180L]  (hidden comment: CL31B106KBHNNNE)
C371  Cap_F: 1µF  VDC_V: 16V  [0603]  (hidden comment: GCM188R71C105KA64J)
C372  VDC_V: 50V  ValueDisplayed: 0.01uF  [0402]  (hidden comment: GRM155R71H103KA88D)
C373  VDC_V: 25V  ValueDisplayed: 0.1uF  [0402]  (hidden comment: GRM155R71E104KE14D)
C374  VDC_V: 25V  ValueDisplayed: 0.1uF  [0402]  (hidden comment: GRM155R71E104KE14D)
C375  Cap_F: 1µF  VDC_V: 16V  [0603]  (hidden comment: GCM188R71C105KA64J)
C376  VDC_V: 50V  ValueDisplayed: 10uF  [1206_180L]  (hidden comment: CL31B106KBHNNNE)
C377  VDC_V: 50V  ValueDisplayed: 68pF  [0402]  (hidden comment: C1005C0G1H680J050BA)
C378  Cap_F: 4.7nF  VDC_V: 50V  [0603]  (hidden comment: C0603X472K5RACTU)
C379  VDC_V: 50V  ValueDisplayed: 68pF  [0402]  (hidden comment: C1005C0G1H680J050BA)
C380  VDC_V: 50V  ValueDisplayed: 0.01uF  [0402]  (hidden comment: GRM155R71H103KA88D)
C381  Cap_F: 1µF  VDC_V: 16V  [0603]  (hidden comment: GCM188R71C105KA64J)
C382  VDC_V: 50V  ValueDisplayed: 10uF  [1206_180L]  (hidden comment: CL31B106KBHNNNE)
D18  value Green  [WL-SMCW_GREEN]  (hidden comment: 150060VS75000)
FB16  BLM15EX331SN1D  [FP-BLM15EX331SN1D_0402-MFG]  (value not drawn)
FB17  BLM15EX331SN1D  [FP-BLM15EX331SN1D_0402-MFG]  (value not drawn)
FB18  BLM15EX331SN1D  [FP-BLM15EX331SN1D_0402-MFG]  (value not drawn)
FB19  BLM15EX331SN1D  [FP-BLM15EX331SN1D_0402-MFG]  (value not drawn)
FB20  BLM15EX331SN1D  [FP-BLM15EX331SN1D_0402-MFG]  (value not drawn)
J22  999-11-113-10-000000  [Mill-Max_999-11-113-10-000000]
J23  999-11-113-10-000000  [Mill-Max_999-11-113-10-000000]
J24  618009231121  [Wurth_618009231121]
J25  61300211121  [WURTH_61300211121]  (value not drawn)
L13  ACT45B-101-2P-TL003  [FP-ACT45B-101-2P-TL003_SMT_4MM5_3MM2-MFG]  (value not drawn)
R382  ValueDisplayed: 499  [0603]  (hidden comment: CRCW0603499RFKEAC)
R383  ValueDisplayed: 10.0k  [0402]  (hidden comment: CRCW040210K0FKED)
R384  ValueDisplayed: 0  [0603]  (hidden comment: RCS06030000Z0EA)
R385  ValueDisplayed: 59.7  [0603]  (hidden comment: RT0603DRE0759R7L)
R386  ValueDisplayed: 59.7  [0603]  (hidden comment: RT0603DRE0759R7L)
R387  ValueDisplayed: 0  [0603]  (hidden comment: RCS06030000Z0EA)
U50  ISOW1044DFM  [DFM0020A-MFG]
U64  TSM24CADBZR  [DBZ0003A-MFG]
U65  TSM24CADBZR  [DBZ0003A-MFG]

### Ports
CAN_EN (bidir), CAN_RX (bidir), CAN_TX (bidir)

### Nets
+3V3: FB17.1
+5V: FB16.1
CAN_GND1: C370.2 C371.2 C372.2 C373.2 FB20.2 U50.4(STB) U50.6(GND1) U50.10(GND1)
GND: FB20.1 J23.1
GND_ISO_CAN: C374.2 C375.2 C376.2 C377.2 C378.1 C379.1 FB19.2 J23.2 J24.3 J24.5 J24.6 J24.10 J24.11 R382.1 U50.15(GND2) U50.16(GND2) U50.17(GND2) U64.2(2_IO) U65.2(2_IO)
VIN_PWR: J22.1
VIN_PWR_CAN: J22.2 J24.4
VP_CAN: C374.1 C375.1 C376.1 D18.2(A) FB18.2 J25.2 U50.20(VISOIN)
CAN_EN: R383.1 U50.8(EN) ; port CAN_EN
CAN_GND2: C380.2 C381.2 C382.2 FB19.1 U50.11(GND2)
CAN_RX: U50.5(RXD) ; port CAN_RX
CAN_TX: U50.3(TXD) ; port CAN_TX
CAN_VDD: C370.1 C371.1 C372.1 FB16.2 U50.9(VDD)
CAN_VIO: C373.1 FB17.2 R383.2 U50.1(VIO)
CANH: L13.1 R384.2 U50.19(CANH)
CANHI: C377.1 J24.7 L13.4 R384.1 R385.2 U65.1(1_IO)
CANL: L13.2 R387.2 U50.18(CANL)
CANLO: C379.2 J24.2 L13.3 R386.1 R387.1 U64.1(1_IO)
VISOOUT: C380.1 C381.1 C382.1 FB18.1 U50.12(VISOOUT) U50.13(VISOOUT)
VP_CAN_SUBD: J24.9 J25.1
NetC378_2: C378.2 R385.1 R386.2
NetD18_1: D18.1(K) R382.2

Not connected (* = marked no-connect by the designer): J24 1* 8*; U50 2(IN)* 7(NC)* 14(OUT)*; U64 3(NC); U65 3(NC)

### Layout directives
net class HV_Nets; net class HV_CAN: CAN_GND2, CANH, CANHI, CANL, CANLO, GND_ISO_CAN, VIN_PWR_CAN, VISOOUT, VP_CAN, VP_CAN_SUBD
net class LV Nets: +3V3, +5V, CAN_GND1, CAN_VDD, CAN_VIO, GND, VIN_PWR

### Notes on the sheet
- (near J22) Daisy Chain Aux PWR to Another System
- CAN Interface
- 5VISO

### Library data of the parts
C370 C376 C382 = CMP-0008802-2: CAP, CERM, 10 uF, 50 V, +/- 10%, X7R, 1206; Manufacturer: Samsung; TaMin_C: -55°C; Polarized: N; SizeAreaWB_mm2: 10.92; Value1: Unknown; U/M: EA; Value: 10uF; TaMax_C: 125°C; SizeZ_mm: 1.8; SizeX_mm: 3.2; SizeY_mm: 1.6; Cap_Case: 1206; SizeArea_mm2: 5.12; Cap_F: 10µF; AEC Category: Q200
C371 C375 C381 = CMP-0079154-1: CAP, CERM, 1 µF, 16 V,+/- 10%, X7R, AEC-Q200 Grade 1, 0603; Manufacturer: MuRata; SizeAreaWB_mm2: 4.68; SizeArea_mm2: 1.28; AEC Qualified: Y; AEC Category: Q200; Value: 1uF; TaMax_C: 125°C; SizeZ_mm: 1; Polarized: N; TaMin_C: -55°C; SizeY_mm: 0.8; U/M: EA; SizeX_mm: 1.6
C372 C380 = CMP-0006674-2: CAP, CERM, 0.01 uF, 50 V, +/- 10%, X7R, 0402; Manufacturer: MuRata; TaMin_C: -55°C; Polarized: N; SizeAreaWB_mm2: 3; Value1: Unknown; U/M: EA; Value: 0.01uF; TaMax_C: 125°C; SizeZ_mm: 0.6; SizeX_mm: 1; SizeY_mm: 0.5; Cap_F: 10nF; AEC Category: Q200
C373 C374 = CMP-0006659-2: CAP, CERM, 0.1 uF, 25 V, +/- 10%, X7R, 0402; Manufacturer: MuRata; TaMin_C: -55°C; Polarized: N; SizeAreaWB_mm2: 3; Value1: Unknown; U/M: EA; Value: 0.1uF; TaMax_C: 125°C; SizeZ_mm: 0.6; SizeX_mm: 1; SizeY_mm: 0.5; Cap_F: 100nF; AEC Category: Q200
C377 C379 = CMP-0006251-2: CAP, CERM, 68 pF, 50 V, +/- 5%, C0G/NP0, 0402; Manufacturer: TDK; TaMin_C: -55°C; Polarized: N; SizeAreaWB_mm2: 3; Value1: Unknown; U/M: EA; Value: 68pF; TaMax_C: 125°C; SizeZ_mm: 0.6; SizeX_mm: 1; SizeY_mm: 0.5; AEC Category: Q200
C378 = CMP-0006987-4: CAP, CERM, 4700 pF, 50 V, +/- 10%, X7R, 0603; Manufacturer: Kemet; TaMin_C: -55°C; Polarized: N; SizeAreaWB_mm2: 4.68; Value1: Unknown; U/M: EA; Value: 4700pF; TaMax_C: 125°C; SizeZ_mm: 1; SizeX_mm: 1.6; SizeY_mm: 0.8; SizeArea_mm2: 1.28; AEC Category: Q200
D18 = CMP-0002894-2: LED, Green, SMD; Manufacturer: Wurth Elektronik; Type: AlInGaP; Value2: 2V; Io_A: 20mA; Value1: W
FB16-FB20 = CMP-0041881-1: Chip Ferrite Bead, 0402, 330Ω @ 100MHz, 0.205Ω, 25%, 1.1A; Manufacturer: Murata; DCR_ohm: 0.205; SizeZ_mm: 0.55mm; AEC Qualified: No; Ciiva Ids: 2806665; Import Ts: 1521856324
J22 J23 = CMP-0055045-1: Shorting Jumper, 7.62mm, 2 Position, Gold, TH; Manufacturer: Mill-Max; CNHeader: FALSE; Gender: Male; Pitch_mm: 7.62; Cert_UL: Y
J24 = CMP-0054820-2: Receptacle, D-Sub, 9 Position, R/A, TH; Manufacturer: Wurth Elektronik; Pitch_mm: 2.77; Gender: Female; Cert_UL: Y; Voltage_V: 125V; ContactFinish: Gold; Row_Count: 2; Current_A: 3A; CNHeader: FALSE; CT: TRUE
J25 = CMP-0054794-2: as J27 on sheet TIDA-1606-Control-Interface-E7
L13 = CMP-0084086-1: 100µH @ 100kHz 2 Line Common Mode Choke Surface Mount 5.8 kOhms @ 10MHz 150mA DCR 2Ohm; Manufacturer: TDK; AEC Grade: Grade 0; Tolerance_%: +50/-30%; AEC Qualified: Yes; Ind_H: 100uH; SizeZ_mm: 3mm; DCR_ohm: 2Ω; Impedance At Frequency: 5800Ω @ 10MHz; Imax_A: 0.15A
R382 = CMP-0082532-1: RES, 499, 1%, 0.1 W, 0603; Manufacturer: Vishay-Dale; Power_W: 100mW; TempCo: 100 ppm/C; SizeAreaWB_mm2: 4.68; Value_Code: 499R; Value: 499; EIA_Code: E96; SizeX_mm: 1.6; SizeY_mm: 0.8; SizeZ_mm: 1; Value2: 0.1W; SizeArea_mm2: 1.28; AEC Qualified: N; VDC_V: 75V; AEC Category: Q200
R383 = CMP-0025958-3: as R375-R379 on sheet TIDA-1606-Control-Interface-E7
R384 R387 = CMP-0081973-1: RES, 0, 0%, 0.25 W, AEC-Q200 Grade 0, 0603; Manufacturer: Vishay-Dale; SizeAreaWB_mm2: 4.68; SizeArea_mm2: 1.28; AEC Qualified: Y; AEC Category: Q200; Value: 0; SizeZ_mm: 1; SizeY_mm: 0.8; Power_W: 250mW; Value2: 0.25W; SizeX_mm: 1.6
R385 R386 = CMP-0025431-3: RES, 59.7, 0.5%, 0.1 W, 0603; Manufacturer: Yageo America; Power_W: 100mW; TempCo: 50 ppm/C; Value_Code: 59R7; U/M: EA; Value: 59.7; EIA_Code: E192; SizeX_mm: 1.6; SizeY_mm: 0.8; SizeZ_mm: 1; Value2: 0.1W; SizeArea_mm2: 1.28; VDC_V: 75V; AEC Category: Q200
U50 = CMP-0092023-2: Reinforced 5-kVRMS Isolated CAN Transceiver with Integrated lowemissions DC-DC Converter; Manufacturer: Texas Instruments; TJmax_C: +150°C; Max Supply Voltage: 5.5V; AEC Qualified: No; Standoff Height: 0.1mm; Nominal Supply Current: 0.3-124mA; CompType: IC; AEC Category: Q200; TaMax_C: +105°C; SizeZ_mm: 3.55mm; Min Supply Voltage: 1.71V; TaMin_C: -40°C
U64 U65 = CMP-0120116-1: ±24 V Low Capacitance Surge Diode for Industrial Networks in SOT-23 Package; Manufacturer: Texas Instruments; SizeZ_mm: 1.12mm; AEC Qualified: No; Breakdown Voltage: 25.5V; Cap_F: 14pF; Clamping Voltage: 35V; Direction: Bidirectional; Ipp: 30A; Number Of Channels: 1; Ppk: 1200W; Standoff Height: 0.01mm; TaMax_C: +125°C; TaMin_C: -40°C; VRWM: 24V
